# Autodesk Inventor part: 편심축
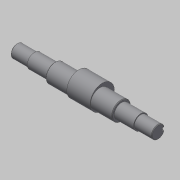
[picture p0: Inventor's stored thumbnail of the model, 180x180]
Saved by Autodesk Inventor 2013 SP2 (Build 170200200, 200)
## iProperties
Created: 2015-10
Part Number: 편심축
Document SubType Name: Modeling
Designer: mdu
Density: 1 g/cm^3
Material: 일반
Mass: 168.947 g
Surface Area: 248.524 cm^2
Volume: 168.947 cm^3
Author: mdu
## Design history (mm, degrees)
sketch "스케치1"
  geometry: L1 (-20.5, -41.331)-(-20.5, 32.669) reference; L2 (7.5, -30.031)-(7.5, 21.369) reference; L3 (135.5, -30.331)-(135.5, 21.669) reference; L4 (121.5, 21.369)-(121.5, -30.031) reference; L5 (184.5, -4.331)-(-57.5, -4.331); L6 (184.5, -4.331)-(184.5, 6.669); L7 (154.5, 8.169)-(121.5, 8.169); L8 (121.5, 8.169)-(121.5, 11.669); L9 (121.5, 11.669)-(7.5, 11.669); L10 (7.5, 11.669)-(7.5, 8.169); L11 (7.5, 8.169)-(-27.5, 8.169); L12 (-27.5, 8.169)-(-27.5, 6.669); L13 (-27.5, 6.669)-(-57.5, 6.669); L14 (-57.5, 6.669)-(-57.5, -4.331); L15 (154.5, 8.169)-(154.5, 6.669); L16 (154.5, 6.669)-(184.5, 6.669); C1 r 32.5 at (64.5, -4.331) reference; 1 further point
  constraints: 24 end point, 8 perpendicular, 5 point on line, 3 parallel, 2 collinear
  dimensions: "d1" = 25 diameter of L11 L5; "d2" = 32 diameter of L9 L5; "d3" = 22 diameter of L13 L5; "d4" = 35 distance of L10.end L11.end; "d5" = 30 distance of L12.end L13.end; "d15" = 33 distance of L7.start L7.end; "d26" = 30 distance of L15.end L6.end
revolve "회전1" sketch "스케치1" stored, may be unused: angle "d6" = 90 deg
node "작업 평면1"
sketch "스케치2"
  geometry: C1 r 16 at (0, 0) reference; C2 r 16 at (0, 0) reference; C3 r 20.75 at (0, 4); C4 r 16 at (0, 0) reference; 1 further point
  constraints: 1 centre point, 1 vertical alignment
  dimensions: "d8" = 41.5 diameter of C3; "d25" = 4 distance of C3.centre C1.centre
extrude "돌출1" join sketch "스케치2" stored distance "d9" = 40; taper "d10" = 0 deg
chamfer "모따기1" distance "d11" = 1; stored, may be unused: second distance "d12" = 2, angle "d13" = 45 deg
node "작업 평면2"
sketch "스케치3"
  geometry: L1 (-15, -10)-(-15, 10) reference; L2 (-15, 3)-(0, 3); L3 (0, -3)-(-15, -3); A1 r 3 centre (0, 0) between (0, -3) and (0, 3); 2 further points
  constraints: 4 end point, 2 perpendicular, 2 point on circle, 2 point on line, 2 tangent, 1 centre point, 1 horizontal alignment, 1 midpoint
  dimensions: "d16" = 18 dimension on A1 L1; "d17" = 6 distance between parallel lines of L3 L2
extrude "돌출2" cut sketch "스케치3" distance "d18" = 3.5; taper "d19" = 0 deg
node "작업 평면3"
node "솔리드1"
mirror "대칭1"
node "참조1"
node "참조2"
node "참조3"
node "참조4"
node "참조5"
node "투영된 루프1"
